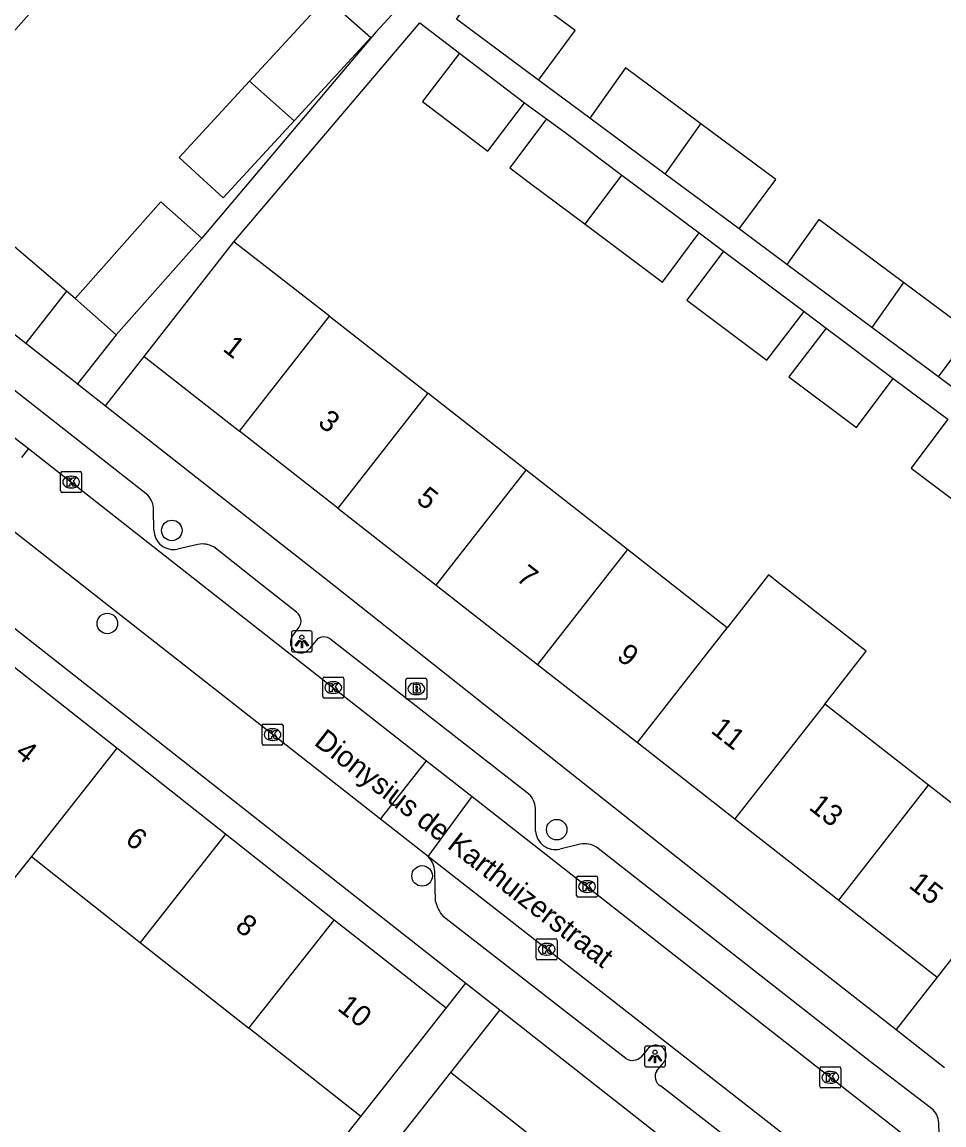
# Model space of a CAD drawing. Extents: x 162812 to 163818, y 381639 to 382470.
# Drawn here: x 162934 to 162977.9, y 381974.3 to 382026.8 of the extents above; entities that cross this region are included whole.
import ezdxf

# ---------------------------------------------------------------- set-up
doc = ezdxf.new("R2010")
doc.units = 0
for name, color, linetype in [('IMGEO_Boom', 7, 'Continuous'), ('IMGEO_Brandkraan', 7, 'Continuous'), ('IMGEO_Groenvoorziening', 7, 'Continuous'), ('IMGEO_Kolk', 7, 'Continuous'), ('IMGEO_Lichtpunt', 7, 'Continuous'), ('IMGEO_Openbare_ruimte_label', 7, 'Continuous'), ('IMGEO_Pand', 7, 'Continuous'), ('IMGEO_Pand_nummerreeks', 7, 'Continuous'), ('IMGEO_Rijbaan_lokaal_open', 7, 'Continuous'), ('IMGEO_Voetpad_halfverhard', 7, 'Continuous'), ('IMGEO_Voetpad_open', 7, 'Continuous')]:
    doc.layers.add(name, color=color, linetype=linetype)

msp = doc.modelspace()

# ---------------------------------------------------------------- linework, layer by layer
at = {"layer": 'IMGEO_Boom'}
for centre in [(162941.132, 382002.606), (162938.059, 381998.174), (162959.468, 381988.356), (162953.054, 381986.152)]:
    msp.add_circle(centre, 0.489, dxfattribs=at)
at = {"layer": 'IMGEO_Brandkraan'}
for p, q in [((162952.279, 381994.641), (162952.279, 381995.493)), ((162952.354, 381995.567), (162953.206, 381995.567)), ((162953.28, 381995.493), (162953.28, 381994.641)), ((162952.767, 381995.347), (162952.792, 381995.347)), ((162953.206, 381994.567), (162952.354, 381994.567)), ((162952.79, 381994.787), (162952.765, 381994.787))]:
    msp.add_line(p, q, dxfattribs=at)
for points in [[(162952.279, 381994.641), (162952.279, 381995.493)], [(162952.354, 381995.567), (162953.206, 381995.567)], [(162953.28, 381995.493), (162953.28, 381994.641)], [(162952.627, 381995.267), (162952.627, 381994.867), (162952.84, 381994.867)], [(162952.858, 381995.267), (162952.627, 381995.267)], [(162952.806, 381995.186), (162952.752, 381995.186), (162952.752, 381995.11)], [(162952.752, 381995.11), (162952.805, 381995.11)], [(162952.814, 381995.034), (162952.752, 381995.034), (162952.752, 381994.953)], [(162952.752, 381994.953), (162952.814, 381994.953)], [(162953.206, 381994.567), (162952.354, 381994.567)]]:
    msp.add_lwpolyline(points, dxfattribs=at)
for centre, radius, start, end in [((162952.356, 381995.491), 0.0765, 91.552, 178.448), ((162952.356, 381995.491), 0.0765, 91.552, 178.448), ((162953.204, 381995.491), 0.0765, 1.552, 88.448), ((162953.204, 381995.491), 0.0765, 1.552, 88.448), ((162952.807, 381995.148), 0.0379, 267.8285, 90.9355), ((162952.815, 381994.993), 0.0404, 269.8759, 90.5077), ((162952.846, 381995.118), 0.251, 268.6676, 293.5347), ((162952.862, 381995.122), 0.145, 59.4692, 91.5367), ((162952.887, 381995.169), 0.0922, 285.5137, 58.1501), ((162952.892, 381994.977), 0.105, 301.3115, 78.989), ((162952.356, 381994.643), 0.0765, 181.552, 268.448), ((162952.356, 381994.643), 0.0765, 181.552, 268.448), ((162953.204, 381994.643), 0.0765, 271.552, 358.448), ((162953.204, 381994.643), 0.0765, 271.552, 358.448)]:
    msp.add_arc(centre, radius, start, end, dxfattribs=at)
for centre, major_axis, ratio, start_param, end_param in [((162952.766, 381995.067), (-0.387, 0.002), 0.722429, 4.712389, 7.853982), ((162952.791, 381995.067), (-0.39, 0.002), 0.717154, 1.570796, 4.712389)]:
    msp.add_ellipse(centre, major_axis=major_axis, ratio=ratio, start_param=start_param, end_param=end_param, dxfattribs=at)
at = {"layer": 'IMGEO_Groenvoorziening'}
msp.add_lwpolyline([(162936.109, 382014.006), (162929.716, 382019.448)], dxfattribs=at)
at = {"layer": 'IMGEO_Kolk'}
for p, q in [((162935.834, 382004.483), (162935.834, 382005.335)), ((162935.909, 382005.409), (162936.761, 382005.409)), ((162936.835, 382005.335), (162936.835, 382004.483)), ((162936.322, 382005.189), (162936.347, 382005.189)), ((162936.761, 382004.409), (162935.909, 382004.409)), ((162936.345, 382004.629), (162936.32, 382004.629)), ((162948.324, 381994.694), (162948.324, 381995.546)), ((162948.399, 381995.62), (162949.251, 381995.62)), ((162948.812, 381995.4), (162948.837, 381995.4)), ((162949.325, 381995.546), (162949.325, 381994.694)), ((162948.835, 381994.84), (162948.81, 381994.84)), ((162949.251, 381994.62), (162948.399, 381994.62)), ((162945.429, 381992.457), (162945.429, 381993.309)), ((162945.504, 381993.383), (162946.356, 381993.383)), ((162946.43, 381993.309), (162946.43, 381992.457)), ((162945.917, 381993.163), (162945.942, 381993.163)), ((162946.356, 381992.383), (162945.504, 381992.383)), ((162945.94, 381992.603), (162945.915, 381992.603)), ((162960.411, 381985.22), (162960.411, 381986.072)), ((162960.486, 381986.146), (162961.338, 381986.146)), ((162960.899, 381985.926), (162960.924, 381985.926)), ((162961.412, 381986.072), (162961.412, 381985.22)), ((162961.338, 381985.146), (162960.486, 381985.146)), ((162960.922, 381985.366), (162960.897, 381985.366)), ((162958.489, 381982.232), (162958.489, 381983.084)), ((162958.564, 381983.158), (162959.416, 381983.158)), ((162958.977, 381982.938), (162959.002, 381982.938)), ((162959.49, 381983.084), (162959.49, 381982.232)), ((162959, 381982.378), (162958.975, 381982.378)), ((162959.416, 381982.158), (162958.564, 381982.158)), ((162972.001, 381976.135), (162972.001, 381976.987)), ((162972.076, 381977.061), (162972.928, 381977.061)), ((162973.002, 381976.987), (162973.002, 381976.135)), ((162972.489, 381976.841), (162972.514, 381976.841)), ((162972.928, 381976.061), (162972.076, 381976.061)), ((162972.512, 381976.281), (162972.487, 381976.281))]:
    msp.add_line(p, q, dxfattribs=at)
for points in [[(162935.834, 382004.483), (162935.834, 382005.335)], [(162935.909, 382005.409), (162936.761, 382005.409)], [(162936.835, 382005.335), (162936.835, 382004.483)], [(162936.155, 382005.109), (162936.278, 382005.109), (162936.278, 382004.958), (162936.408, 382005.109), (162936.572, 382005.109), (162936.426, 382004.958), (162936.579, 382004.709), (162936.427, 382004.709), (162936.342, 382004.873), (162936.278, 382004.806), (162936.278, 382004.709), (162936.155, 382004.709), (162936.155, 382005.109)], [(162936.761, 382004.409), (162935.909, 382004.409)], [(162948.324, 381994.694), (162948.324, 381995.546)], [(162948.399, 381995.62), (162949.251, 381995.62)], [(162949.325, 381995.546), (162949.325, 381994.694)], [(162948.645, 381995.32), (162948.768, 381995.32), (162948.768, 381995.169), (162948.898, 381995.32), (162949.062, 381995.32), (162948.916, 381995.169), (162949.069, 381994.92), (162948.917, 381994.92), (162948.832, 381995.084), (162948.768, 381995.017), (162948.768, 381994.92), (162948.645, 381994.92), (162948.645, 381995.32)], [(162949.251, 381994.62), (162948.399, 381994.62)], [(162945.429, 381992.457), (162945.429, 381993.309)], [(162945.504, 381993.383), (162946.356, 381993.383)], [(162946.43, 381993.309), (162946.43, 381992.457)], [(162945.75, 381993.083), (162945.873, 381993.083), (162945.873, 381992.932), (162946.003, 381993.083), (162946.167, 381993.083), (162946.021, 381992.932), (162946.174, 381992.683), (162946.022, 381992.683), (162945.937, 381992.847), (162945.873, 381992.78), (162945.873, 381992.683), (162945.75, 381992.683), (162945.75, 381993.083)], [(162946.356, 381992.383), (162945.504, 381992.383)], [(162960.411, 381985.22), (162960.411, 381986.072)], [(162960.486, 381986.146), (162961.338, 381986.146)], [(162961.412, 381986.072), (162961.412, 381985.22)], [(162960.732, 381985.846), (162960.855, 381985.846), (162960.855, 381985.695), (162960.985, 381985.846), (162961.149, 381985.846), (162961.003, 381985.695), (162961.156, 381985.446), (162961.004, 381985.446), (162960.919, 381985.61), (162960.855, 381985.543), (162960.855, 381985.446), (162960.732, 381985.446), (162960.732, 381985.846)], [(162961.338, 381985.146), (162960.486, 381985.146)], [(162958.489, 381982.232), (162958.489, 381983.084)], [(162958.564, 381983.158), (162959.416, 381983.158)], [(162958.81, 381982.858), (162958.933, 381982.858), (162958.933, 381982.707), (162959.063, 381982.858), (162959.227, 381982.858), (162959.081, 381982.707), (162959.234, 381982.458), (162959.082, 381982.458), (162958.997, 381982.622), (162958.933, 381982.555), (162958.933, 381982.458), (162958.81, 381982.458), (162958.81, 381982.858)], [(162959.49, 381983.084), (162959.49, 381982.232)], [(162959.416, 381982.158), (162958.564, 381982.158)], [(162972.001, 381976.135), (162972.001, 381976.987)], [(162972.076, 381977.061), (162972.928, 381977.061)], [(162973.002, 381976.987), (162973.002, 381976.135)], [(162972.322, 381976.761), (162972.445, 381976.761), (162972.445, 381976.61), (162972.575, 381976.761), (162972.739, 381976.761), (162972.593, 381976.61), (162972.746, 381976.361), (162972.594, 381976.361), (162972.509, 381976.525), (162972.445, 381976.458), (162972.445, 381976.361), (162972.322, 381976.361), (162972.322, 381976.761)], [(162972.928, 381976.061), (162972.076, 381976.061)]]:
    msp.add_lwpolyline(points, dxfattribs=at)
for centre, start, end in [((162935.911, 382005.333), 91.552, 178.448), ((162935.911, 382005.333), 91.552, 178.448), ((162936.759, 382005.333), 1.552, 88.448), ((162936.759, 382005.333), 1.552, 88.448), ((162935.911, 382004.485), 181.552, 268.448), ((162935.911, 382004.485), 181.552, 268.448), ((162936.759, 382004.485), 271.552, 358.448), ((162936.759, 382004.485), 271.552, 358.448), ((162948.401, 381995.544), 91.552, 178.448), ((162948.401, 381995.544), 91.552, 178.448), ((162949.249, 381995.544), 1.552, 88.448), ((162949.249, 381995.544), 1.552, 88.448), ((162948.401, 381994.696), 181.552, 268.448), ((162948.401, 381994.696), 181.552, 268.448), ((162949.249, 381994.696), 271.552, 358.448), ((162949.249, 381994.696), 271.552, 358.448), ((162945.506, 381993.307), 91.552, 178.448), ((162945.506, 381993.307), 91.552, 178.448), ((162946.354, 381993.307), 1.552, 88.448), ((162946.354, 381993.307), 1.552, 88.448), ((162945.506, 381992.459), 181.552, 268.448), ((162945.506, 381992.459), 181.552, 268.448), ((162946.354, 381992.459), 271.552, 358.448), ((162946.354, 381992.459), 271.552, 358.448), ((162960.488, 381986.07), 91.552, 178.448), ((162960.488, 381986.07), 91.552, 178.448), ((162961.336, 381986.07), 1.552, 88.448), ((162961.336, 381986.07), 1.552, 88.448), ((162960.488, 381985.222), 181.552, 268.448), ((162960.488, 381985.222), 181.552, 268.448), ((162961.336, 381985.222), 271.552, 358.448), ((162961.336, 381985.222), 271.552, 358.448), ((162958.566, 381983.082), 91.552, 178.448), ((162958.566, 381983.082), 91.552, 178.448), ((162959.414, 381983.082), 1.552, 88.448), ((162959.414, 381983.082), 1.552, 88.448), ((162958.566, 381982.234), 181.552, 268.448), ((162958.566, 381982.234), 181.552, 268.448), ((162959.414, 381982.234), 271.552, 358.448), ((162959.414, 381982.234), 271.552, 358.448), ((162972.078, 381976.985), 91.552, 178.448), ((162972.078, 381976.985), 91.552, 178.448), ((162972.926, 381976.985), 1.552, 88.448), ((162972.926, 381976.985), 1.552, 88.448), ((162972.078, 381976.137), 181.552, 268.448), ((162972.078, 381976.137), 181.552, 268.448), ((162972.926, 381976.137), 271.552, 358.448), ((162972.926, 381976.137), 271.552, 358.448)]:
    msp.add_arc(centre, 0.0765, start, end, dxfattribs=at)
for centre, major_axis, ratio, start_param, end_param in [((162936.321, 382004.909), (-0.387, 0.002), 0.722429, 4.712389, 7.853982), ((162936.346, 382004.909), (-0.39, 0.002), 0.717154, 1.570796, 4.712389), ((162948.811, 381995.12), (-0.387, 0.002), 0.722429, 4.712389, 7.853982), ((162948.836, 381995.12), (-0.39, 0.002), 0.717154, 1.570796, 4.712389), ((162945.916, 381992.883), (-0.387, 0.002), 0.722429, 4.712389, 7.853982), ((162945.941, 381992.883), (-0.39, 0.002), 0.717154, 1.570796, 4.712389), ((162960.898, 381985.646), (-0.387, 0.002), 0.722429, 4.712389, 7.853982), ((162960.923, 381985.646), (-0.39, 0.002), 0.717154, 1.570796, 4.712389), ((162958.976, 381982.658), (-0.387, 0.002), 0.722429, 4.712389, 7.853982), ((162959.001, 381982.658), (-0.39, 0.002), 0.717154, 1.570796, 4.712389), ((162972.488, 381976.561), (-0.387, 0.002), 0.722429, 4.712389, 7.853982), ((162972.513, 381976.561), (-0.39, 0.002), 0.717154, 1.570796, 4.712389)]:
    msp.add_ellipse(centre, major_axis=major_axis, ratio=ratio, start_param=start_param, end_param=end_param, dxfattribs=at)
at = {"layer": 'IMGEO_Lichtpunt'}
for p, q in [((162946.827, 381997.723), (162946.827, 381996.916)), ((162946.827, 381997.723), (162946.827, 381996.916)), ((162947.729, 381997.818), (162946.921, 381997.818)), ((162947.729, 381997.818), (162946.921, 381997.818)), ((162947.823, 381996.916), (162947.823, 381997.723)), ((162947.823, 381996.916), (162947.823, 381997.723)), ((162946.921, 381996.822), (162947.729, 381996.822)), ((162946.921, 381996.822), (162947.729, 381996.822)), ((162964.553, 381978.053), (162963.745, 381978.053)), ((162964.553, 381978.053), (162963.745, 381978.053)), ((162963.651, 381977.958), (162963.651, 381977.151)), ((162963.651, 381977.958), (162963.651, 381977.151)), ((162964.647, 381977.151), (162964.647, 381977.958)), ((162964.647, 381977.151), (162964.647, 381977.958)), ((162963.745, 381977.057), (162964.553, 381977.057)), ((162963.745, 381977.057), (162964.553, 381977.057))]:
    msp.add_line(p, q, dxfattribs=at)
for points in [[(162947.201, 381997.387), (162947.24, 381997.359), (162947.052, 381997.097), (162947.014, 381997.124), (162947.201, 381997.387)], [(162947.303, 381997.339), (162947.35, 381997.339), (162947.35, 381997.017), (162947.303, 381997.017), (162947.303, 381997.339)], [(162947.413, 381997.359), (162947.451, 381997.386), (162947.638, 381997.124), (162947.599, 381997.096), (162947.413, 381997.359)], [(162964.025, 381977.622), (162964.064, 381977.594), (162963.876, 381977.332), (162963.838, 381977.359), (162964.025, 381977.622)], [(162964.127, 381977.574), (162964.174, 381977.574), (162964.174, 381977.252), (162964.127, 381977.252), (162964.127, 381977.574)], [(162964.237, 381977.594), (162964.275, 381977.621), (162964.462, 381977.359), (162964.423, 381977.331), (162964.237, 381977.594)]]:
    msp.add_lwpolyline(points, dxfattribs=at)
for centre in [(162947.326, 381997.521), (162964.15, 381977.756)]:
    msp.add_circle(centre, 0.0994, dxfattribs=at)
for centre, start, end in [((162946.921, 381997.723), 90, 180), ((162946.921, 381997.723), 90, 180), ((162947.729, 381997.723), 0, 90), ((162947.729, 381997.723), 0, 90), ((162946.921, 381996.916), 180, 270), ((162946.921, 381996.916), 180, 270), ((162947.729, 381996.916), 270, 0), ((162947.729, 381996.916), 270, 360), ((162963.745, 381977.958), 90, 180), ((162963.745, 381977.958), 90, 180), ((162964.553, 381977.958), 0, 90), ((162964.553, 381977.958), 0, 90), ((162963.745, 381977.151), 180, 270), ((162963.745, 381977.151), 180, 270), ((162964.553, 381977.151), 270, 0), ((162964.553, 381977.151), 270, 360)]:
    msp.add_arc(centre, 0.0946, start, end, dxfattribs=at)
at = {"layer": 'IMGEO_Pand'}
for points in [[(162933.576, 382026.335), (162937.377, 382030.619)], [(162958.604, 382024.05), (162960.351, 382026.405), (162956.442, 382029.305), (162954.826, 382027.127)], [(162944.834, 382024.004), (162948.488, 382027.971), (162950.617, 382026.083), (162946.963, 382022.115)], [(162958.604, 382024.05), (162954.695, 382026.951), (162954.826, 382027.127)], [(162954.839, 382025.332), (162953.081, 382023.027), (162956.179, 382020.663), (162957.937, 382022.967)], [(162954.839, 382025.332), (162957.937, 382022.967)], [(162966.333, 382021.966), (162962.747, 382024.627), (162961.051, 382022.235)], [(162946.963, 382022.115), (162943.577, 382018.438), (162941.484, 382020.366), (162944.834, 382024.004)], [(162946.963, 382022.115), (162944.834, 382024.004)], [(162958.986, 382022.209), (162957.237, 382019.871), (162958.161, 382019.179), (162960.826, 382017.184)], [(162958.986, 382022.209), (162959.911, 382021.516), (162962.576, 382019.521)], [(162964.637, 382019.574), (162961.051, 382022.235)], [(162964.637, 382019.574), (162966.333, 382021.966)], [(162968.158, 382016.961), (162969.905, 382019.315), (162966.333, 382021.966)], [(162960.826, 382017.184), (162962.576, 382019.521)], [(162962.576, 382019.521), (162966.248, 382016.773)], [(162968.158, 382016.961), (162964.637, 382019.574)], [(162942.565, 382016.517), (162940.612, 382018.249), (162936.53, 382013.648)], [(162960.826, 382017.184), (162964.499, 382014.435), (162966.248, 382016.773)], [(162975.993, 382014.411), (162971.948, 382017.413), (162970.431, 382015.273)], [(162942.565, 382016.517), (162938.483, 382011.916)], [(162939.816, 382010.885), (162942.897, 382014.824), (162944.094, 382016.355)], [(162948.636, 382012.802), (162944.094, 382016.355)], [(162967.409, 382015.903), (162965.66, 382013.566), (162969.481, 382010.706), (162971.253, 382013.027)], [(162967.409, 382015.903), (162971.253, 382013.027)], [(162974.477, 382012.271), (162970.431, 382015.273)], [(162975.993, 382014.411), (162974.477, 382012.271)], [(162977.656, 382009.912), (162979.218, 382012.018), (162975.993, 382014.411)], [(162938.483, 382011.916), (162936.53, 382013.648)], [(162944.358, 382007.332), (162948.636, 382012.802)], [(162948.636, 382012.802), (162953.325, 382009.134)], [(162972.303, 382012.24), (162970.532, 382009.919), (162973.75, 382007.511), (162975.499, 382009.848)], [(162972.303, 382012.24), (162975.499, 382009.848)], [(162977.656, 382009.912), (162974.477, 382012.271)], [(162939.816, 382010.885), (162944.358, 382007.332)], [(162953.325, 382009.134), (162949.047, 382003.664)], [(162958.01, 382005.47), (162953.325, 382009.134)], [(162978.099, 382007.902), (162976.349, 382005.565), (162977.319, 382004.839), (162979.668, 382003.08)], [(162949.047, 382003.664), (162944.358, 382007.332)], [(162953.732, 382000), (162958.01, 382005.47)], [(162962.836, 382001.695), (162958.01, 382005.47)], [(162949.047, 382003.664), (162953.732, 382000)], [(162962.836, 382001.695), (162961.51, 382000), (162958.557, 381996.225)], [(162967.592, 381997.974), (162965.002, 382000), (162962.836, 382001.695)], [(162972.239, 381994.339), (162974.203, 381996.85), (162970.176, 382000), (162969.556, 382000.485), (162969.177, 382000), (162967.592, 381997.974)], [(162953.732, 382000), (162958.557, 381996.225)], [(162963.313, 381992.504), (162967.592, 381997.974)], [(162938.512, 381992.231), (162933.332, 381996.32)], [(162958.557, 381996.225), (162963.313, 381992.504)], [(162972.239, 381994.339), (162967.96, 381988.87)], [(162977.185, 381990.47), (162972.239, 381994.339)], [(162938.512, 381992.231), (162934.446, 381987.08)], [(162943.692, 381988.142), (162938.512, 381992.231)], [(162963.313, 381992.504), (162967.96, 381988.87)], [(162934.446, 381987.08), (162931.943, 381983.964), (162926.705, 381988.096), (162929.266, 381991.169)], [(162972.907, 381985), (162977.185, 381990.47)], [(162981.874, 381986.802), (162977.185, 381990.47)], [(162967.96, 381988.87), (162972.907, 381985)], [(162943.692, 381988.142), (162939.626, 381982.99)], [(162948.873, 381984.052), (162943.692, 381988.142)], [(162934.446, 381987.08), (162939.626, 381982.99)], [(162981.874, 381986.802), (162980.676, 381985.271), (162977.594, 381981.333)], [(162972.907, 381985), (162977.594, 381981.333)], [(162944.807, 381978.9), (162948.873, 381984.052)], [(162954.197, 381979.849), (162948.873, 381984.052)], [(162939.626, 381982.99), (162944.807, 381978.9)], [(162950.13, 381974.698), (162951.099, 381975.925), (162954.197, 381979.849)], [(162950.13, 381974.698), (162944.807, 381978.9)], [(162954.411, 381976.794), (162951.314, 381972.87), (162950.309, 381971.597)], [(162959.747, 381972.582), (162954.411, 381976.794)]]:
    msp.add_lwpolyline(points, dxfattribs=at)
at = {"layer": 'IMGEO_Rijbaan_lokaal_open'}
for points in [[(162920.977, 382016.827), (162934.305, 382006.499)], [(162934.305, 382006.499), (162933.979, 382006.075)], [(162934.305, 382006.499), (162942.597, 382000), (162953.262, 381991.64)], [(162951.066, 381988.858), (162936.855, 382000), (162933.017, 382003.009)], [(162951.066, 381988.858), (162953.262, 381991.64)], [(162953.262, 381991.64), (162955.442, 381989.931)], [(162953.337, 381987.077), (162955.442, 381989.931)], [(162955.442, 381989.931), (162973.286, 381975.945), (163000, 381955.072), (163016.211, 381942.406)], [(162953.337, 381987.077), (162951.066, 381988.858)], [(163014.048, 381939.637), (163000, 381950.614), (162953.337, 381987.077)]]:
    msp.add_lwpolyline(points, dxfattribs=at)
at = {"layer": 'IMGEO_Voetpad_halfverhard'}
for points in [[(162954.197, 381979.849), (162955.144, 381981.044)], [(162956.756, 381979.777), (162954.411, 381976.794)], [(162938.205, 381964.268), (162940.392, 381962.373), (162950.13, 381974.698)]]:
    msp.add_lwpolyline(points, dxfattribs=at)
at = {"layer": 'IMGEO_Voetpad_open'}
for points in [[(162952.397, 382028.016), (162950.853, 382026.339), (162942.565, 382016.517)], [(162944.094, 382016.355), (162952.939, 382026.783), (162954.839, 382025.332)], [(162961.051, 382022.235), (162958.604, 382024.05)], [(162918.865, 382023.545), (162934.177, 382011.519)], [(162957.937, 382022.967), (162958.986, 382022.209)], [(162970.431, 382015.273), (162968.158, 382016.961)], [(162966.248, 382016.773), (162967.409, 382015.903)], [(162936.109, 382014.006), (162934.177, 382011.519)], [(162936.53, 382013.648), (162936.109, 382014.006)], [(162939.983, 382004.281), (162929.241, 382012.721)], [(162971.253, 382013.027), (162972.303, 382012.24)], [(162938.483, 382011.916), (162936.637, 382009.587)], [(162934.177, 382011.519), (162936.523, 382009.676), (162936.637, 382009.587)], [(162937.978, 382008.533), (162939.816, 382010.885)], [(162936.637, 382009.587), (162937.978, 382008.533)], [(162975.499, 382009.848), (162978.099, 382007.902)], [(162979.689, 382008.403), (162977.656, 382009.912)], [(162937.978, 382008.533), (162948.843, 382000), (162969.071, 381983.988), (162975.634, 381978.836)], [(162940.282, 382002.624), (162940.266, 382003.579)], [(162942.379, 382001.938), (162941.398, 382001.717)], [(162947.073, 381998.709), (162945.434, 382000), (162943.127, 382001.817)], [(162928.941, 382001.641), (162955.144, 381981.044)], [(162946.87, 381997.549), (162947.203, 381997.996)], [(162948.002, 381997.369), (162947.685, 381996.983)], [(162958.201, 381989.998), (162948.72, 381997.393)], [(162958.46, 381988.284), (162958.451, 381989.271)], [(162960.591, 381987.661), (162959.613, 381987.425)], [(162977.394, 381975.008), (162974.414, 381977.295), (162961.356, 381987.521)], [(162953.701, 381984.94), (162953.662, 381986.368)], [(162962.767, 381977.456), (162954.061, 381984.224)], [(162977.594, 381981.333), (162975.634, 381978.836)], [(162955.144, 381981.044), (162956.756, 381979.777)], [(162956.756, 381979.777), (162998.706, 381946.802)], [(162975.634, 381978.836), (162977.939, 381977.029)], [(162963.799, 381977.905), (162963.489, 381977.542)], [(162964.236, 381976.878), (162964.532, 381977.242)], [(162973.091, 381969.397), (162964.417, 381976.15)], [(162977.713, 381973.306), (162977.665, 381974.294)]]:
    msp.add_lwpolyline(points, dxfattribs=at)
for centre, radius, start, end in [((162939.284, 382003.591), 0.982, 359.2878, 44.6243), ((162941.21, 382002.625), 0.928, 180.0714, 281.7255), ((162942.593, 382000.891), 1.069, 60.057, 101.5653), ((162946.761, 381998.284), 0.527, 326.9158, 53.7505), ((162947.276, 381997.264), 0.496, 144.9802, 325.4615), ((162948.372, 381997.043), 0.494, 45.2111, 138.6179), ((162957.482, 381989.344), 0.972, 355.6879, 42.2662), ((162959.41, 381988.356), 0.953, 184.3558, 282.271), ((162960.809, 381986.693), 0.993, 56.5661, 102.6924), ((162952.588, 381986.305), 1.076, 3.3753, 45.8774), ((162955.16, 381985.225), 1.487, 191.0597, 222.3262), ((162964.188, 381977.598), 0.495, 314.0644, 141.6768), ((162963.074, 381977.953), 0.584, 238.3119, 315.2735), ((162964.671, 381976.6), 0.517, 147.4265, 240.4978), ((162976.767, 381974.362), 0.9, 355.6934, 45.8753)]:
    msp.add_arc(centre, radius, start, end, dxfattribs=at)

# ---------------------------------------------------------------- texts
at = {"layer": 'IMGEO_Openbare_ruimte_label'}
msp.add_text('Dionysius de Karthuizerstraat', height=1, rotation=322.1903, dxfattribs=at).set_placement((162947.86, 381992.432))
at = {"layer": 'IMGEO_Pand_nummerreeks'}
for s, rotation, p in [('1', 321.9656, (162943.513, 382011.193)), ('3', 321.9656, (162948.038, 382007.652)), ('5', 321.972, (162952.725, 382003.986)), ('7', 321.961, (162957.481, 382000.268)), ('9', 321.9655, (162962.273, 381996.517)), ('11', 321.9655, (162966.76, 381993.008)), ('4', 321.7114, (162933.619, 381991.915)), ('13', 321.9655, (162971.429, 381989.355)), ('6', 321.7114, (162938.857, 381987.78)), ('15', 321.9655, (162976.188, 381985.633)), ('8', 321.7114, (162944.097, 381983.644)), ('10', 321.7114, (162948.971, 381979.796))]:
    msp.add_text(s, height=1, rotation=rotation, dxfattribs=at).set_placement(p)

doc.saveas('drawing.dxf')
